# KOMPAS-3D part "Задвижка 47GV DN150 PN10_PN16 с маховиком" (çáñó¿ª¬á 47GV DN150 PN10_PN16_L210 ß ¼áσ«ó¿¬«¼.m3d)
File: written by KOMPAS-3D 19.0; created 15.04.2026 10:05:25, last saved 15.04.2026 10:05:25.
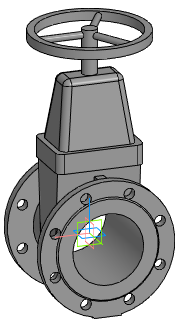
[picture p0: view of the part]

Document properties: Автор: Евгений; Полное имя файла: Z:\3.Личные\kachalov\3d для проектировщиков\2.1 Тип 47GV, 47GV.Z\Задвижка 47GV_DN40-DN600\stp_Задвижка 47GV\Задвижка 47GV DN150 PN10_PN16_L210 с маховиком.m3d

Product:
- Part/product: Задвижка 47GV DN150 PN10_PN16 с маховиком

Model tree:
1. Операция без истории:1  (labels: Задвижка 47GV DN150 PN10_PN16 с маховиком)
